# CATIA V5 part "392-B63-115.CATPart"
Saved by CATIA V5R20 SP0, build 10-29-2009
Part number: 392-B63-115
Definition: NONE
Nomenclature: 392-B63-115
Source: Unknown
Description: 392-B63-115
Bounding box of the stored display mesh (mm): x 0 to 115, y -31.429 to 31.429, z -31.1 to 31.1
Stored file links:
  C:\Users\Utente\Desktop\IO LAVORO\3D X SITO CF\X SITO\3D files 392B\392-B63-115.CATPart
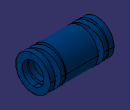
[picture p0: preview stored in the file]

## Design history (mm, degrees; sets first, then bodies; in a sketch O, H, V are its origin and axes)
Body1 "392-B63-115" (main body)
  Solid1: solid without history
